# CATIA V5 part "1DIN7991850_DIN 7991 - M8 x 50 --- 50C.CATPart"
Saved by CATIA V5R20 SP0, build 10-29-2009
Part number: 1DIN7991850_DIN 7991 - M8 x 50 --- 50C
Revision: ANY
Definition: UNKNOWN
Nomenclature: 1DIN7991850_DIN 7991 - M8 x 50 --- 50C
Source: Unknown
Bounding box of the stored display mesh (mm): x 0 to 50, y -7.59 to 7.59, z -7.785 to 7.785
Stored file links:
  C:\Users\Utente\Desktop\IO LAVORO\3D X SITO CF\CUMSA\3D files PO\PO 340850\1DIN7991850_DIN 7991 - M8 x 50 --- 50C.CATPart
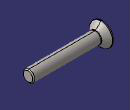
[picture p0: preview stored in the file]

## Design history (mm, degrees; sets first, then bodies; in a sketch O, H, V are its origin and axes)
Body1 "Hex" (main body)
  Solid1: solid without history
